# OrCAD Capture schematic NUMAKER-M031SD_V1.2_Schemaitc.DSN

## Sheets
1 Nu-Link2-Me: size A3; title: Nu-Link2-Me; rev: 1.0; company: CMHuang; note: Nu-Link2-Me
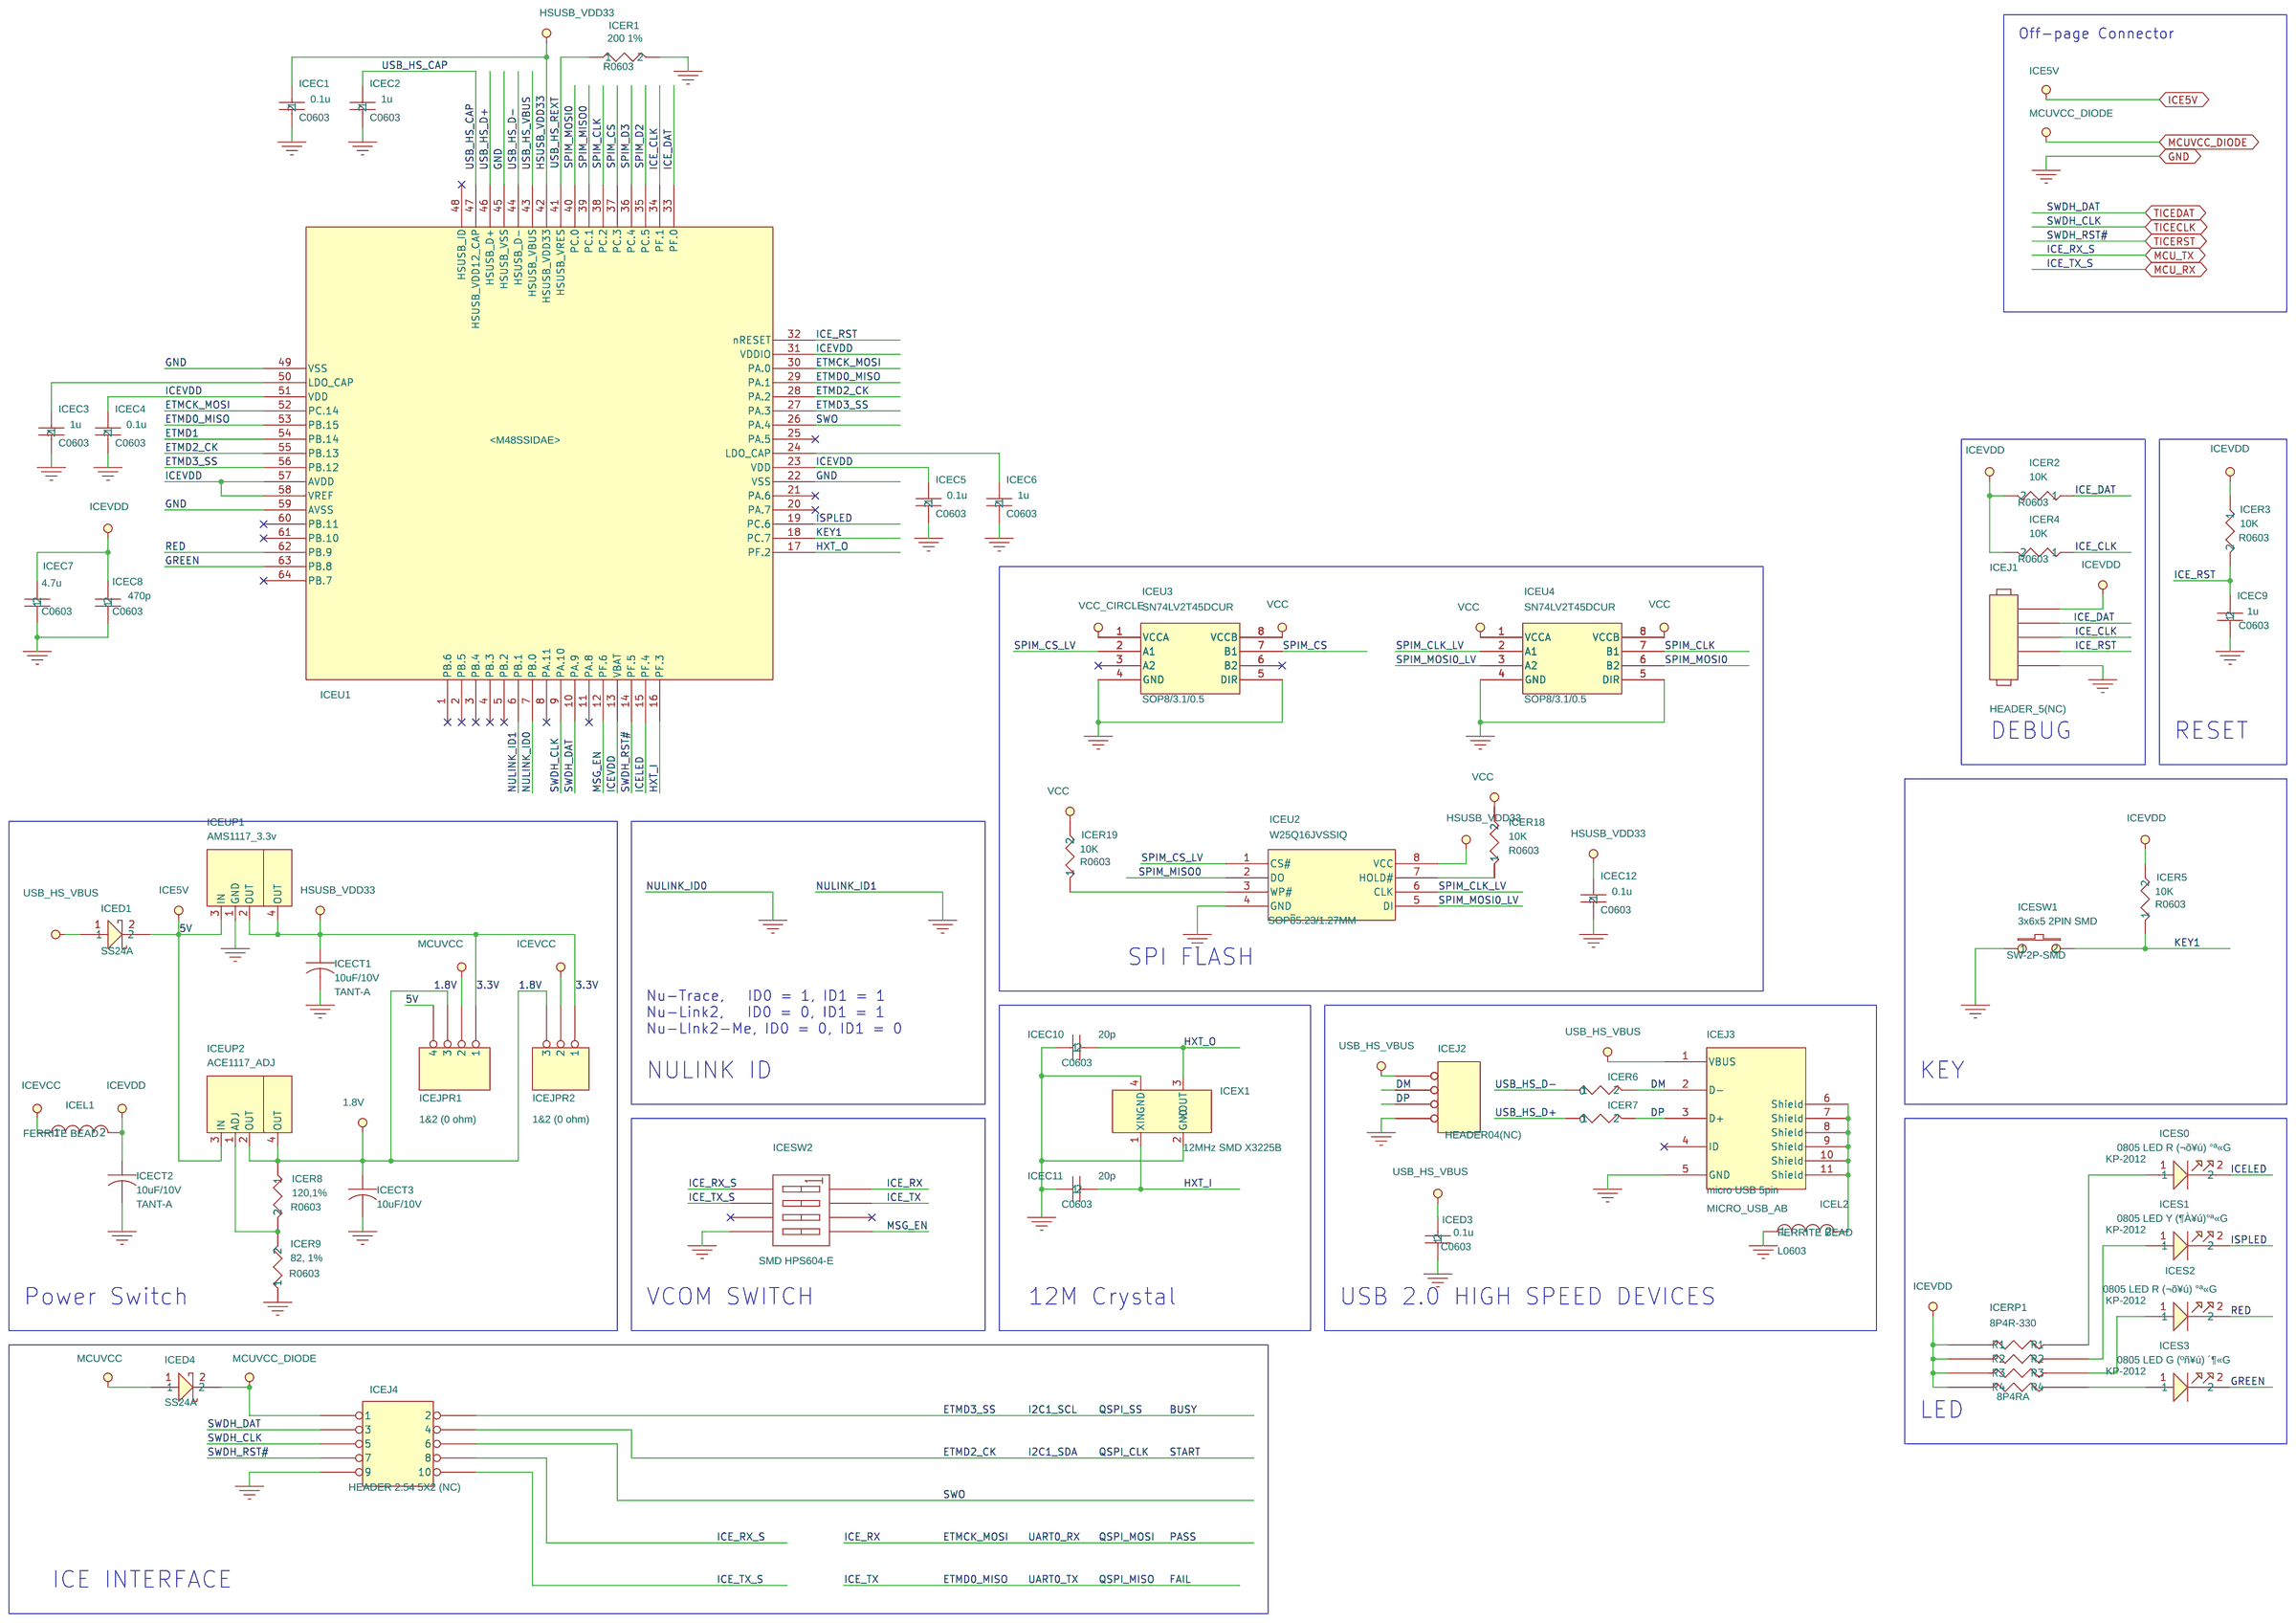
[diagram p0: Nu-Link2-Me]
2 M031SD2AE: size Custom; title: M031SD2AE; rev: v1.2; note: NuMaker-M031SD
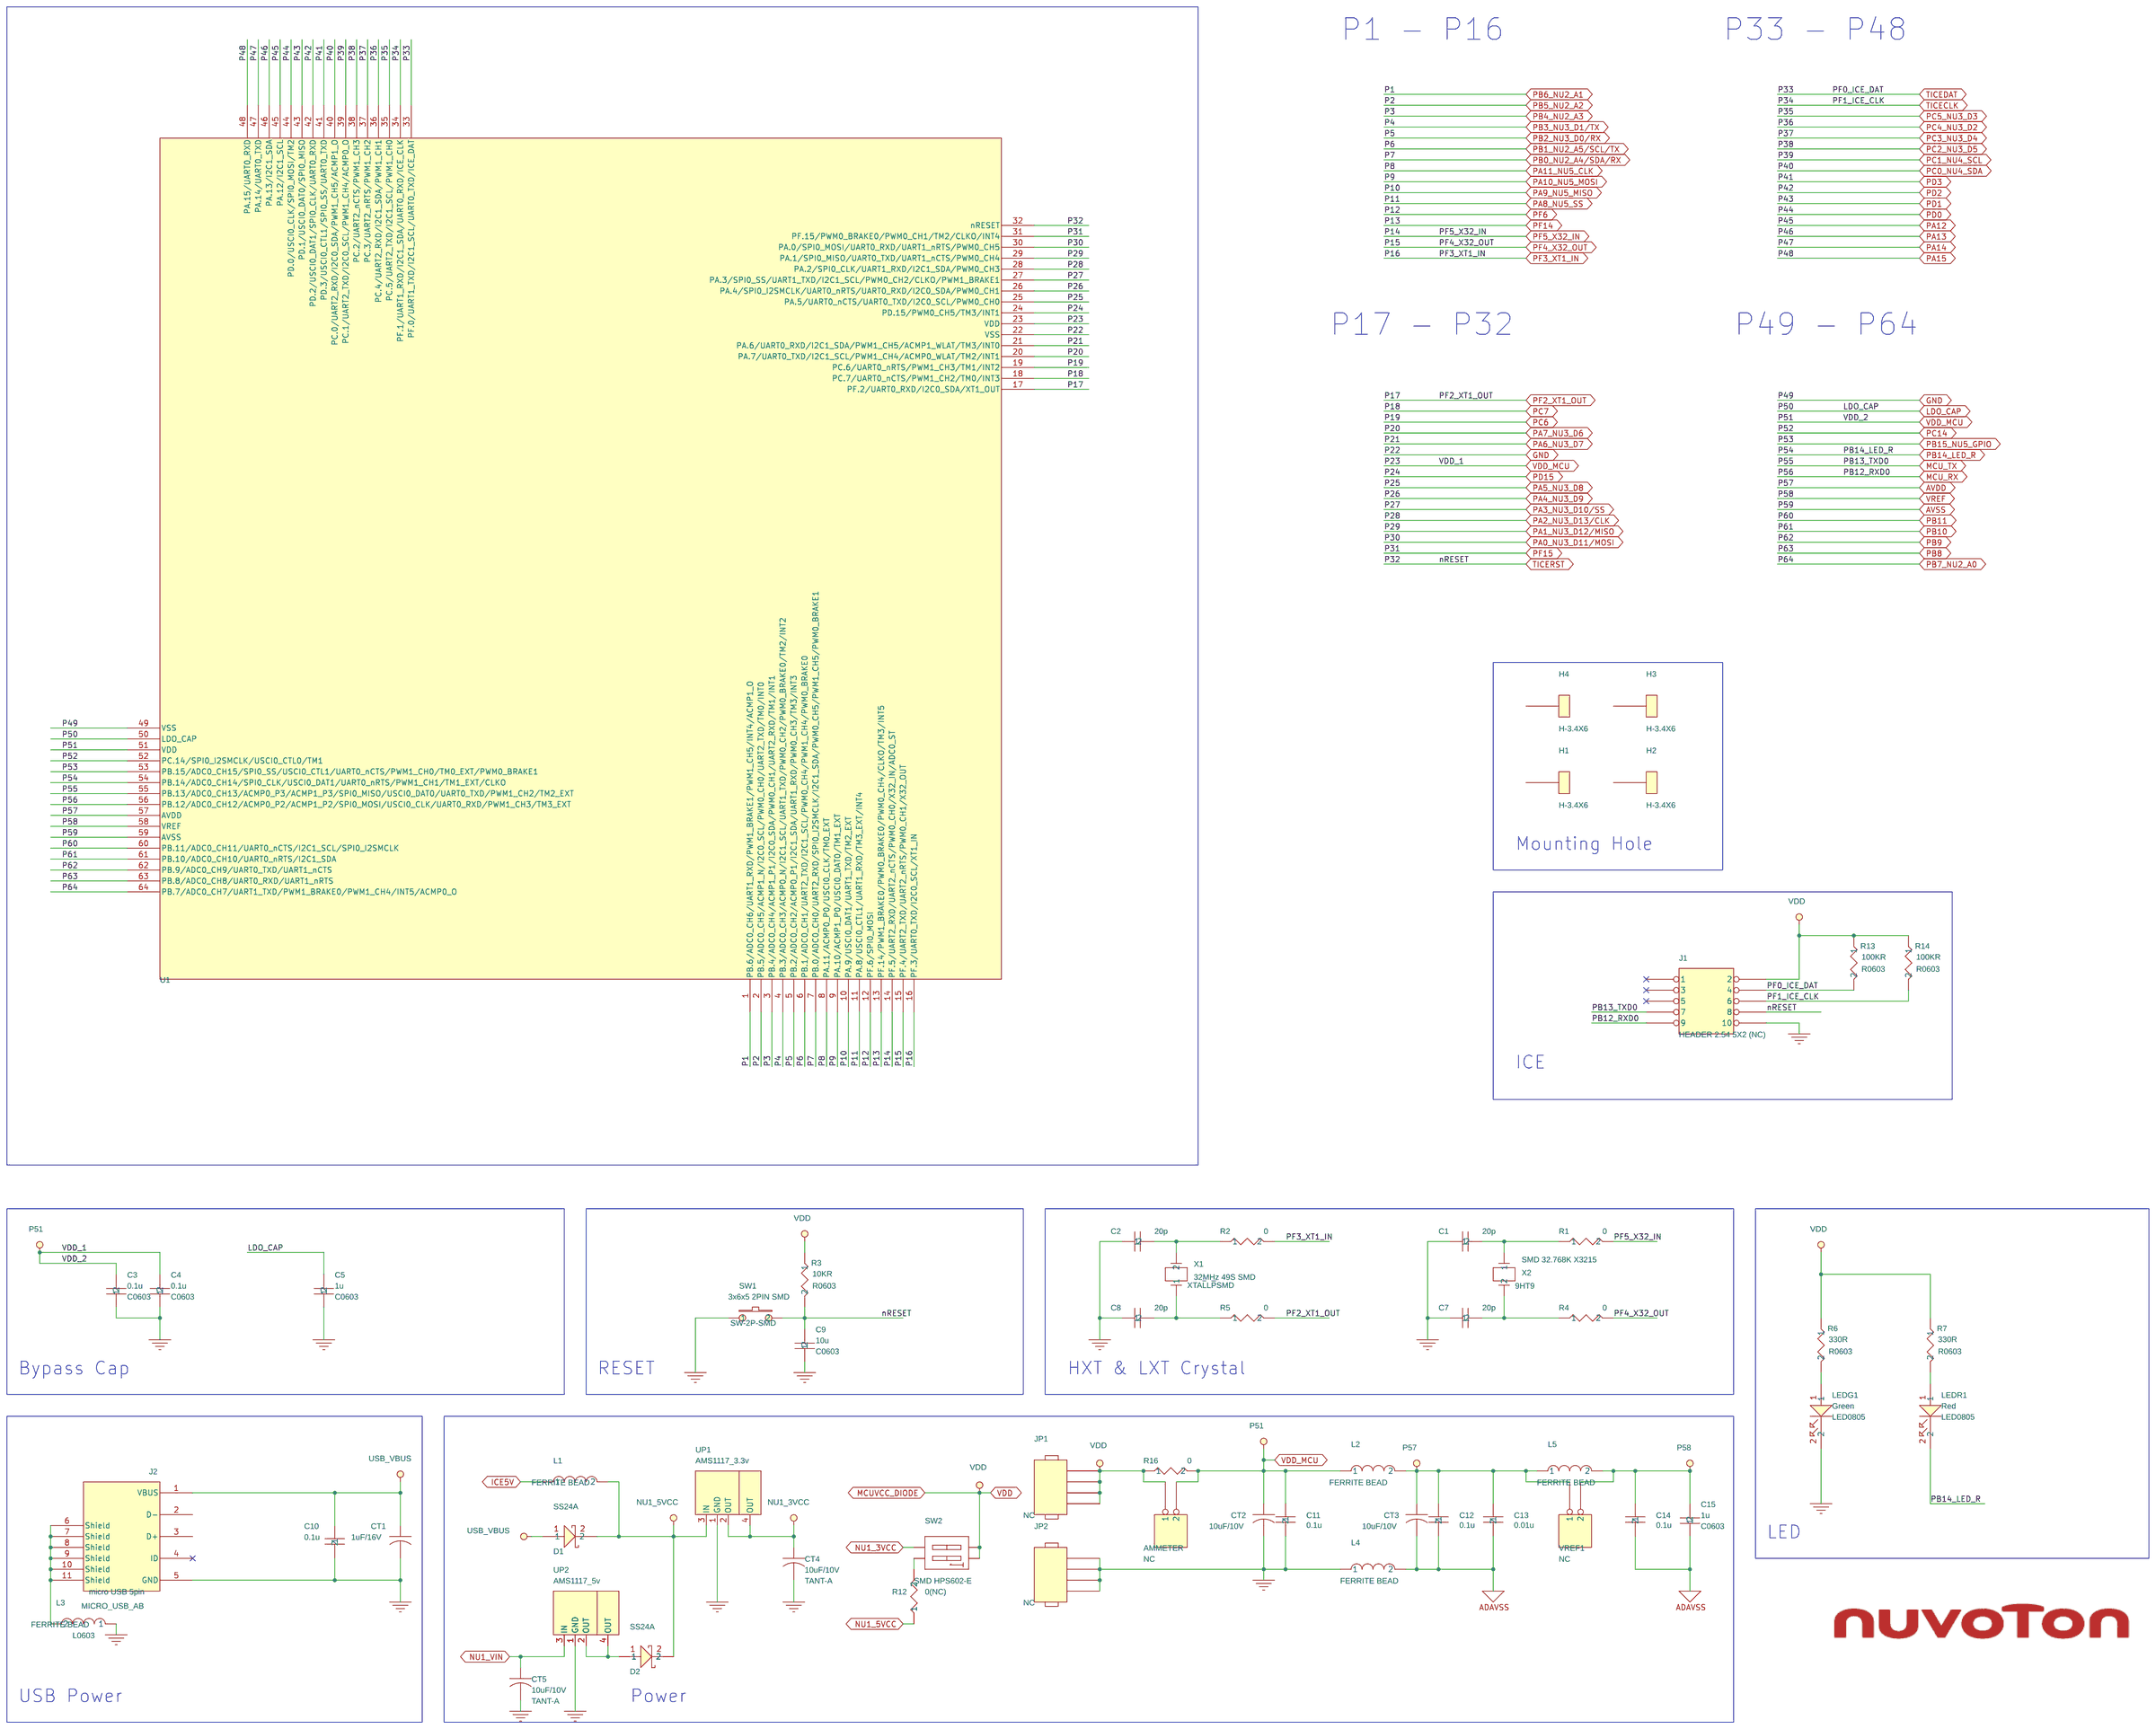
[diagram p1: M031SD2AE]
3 Ext. Connector: size Custom; title: Ext. Connector; rev: v1.2; note: NuMaker-M031SD
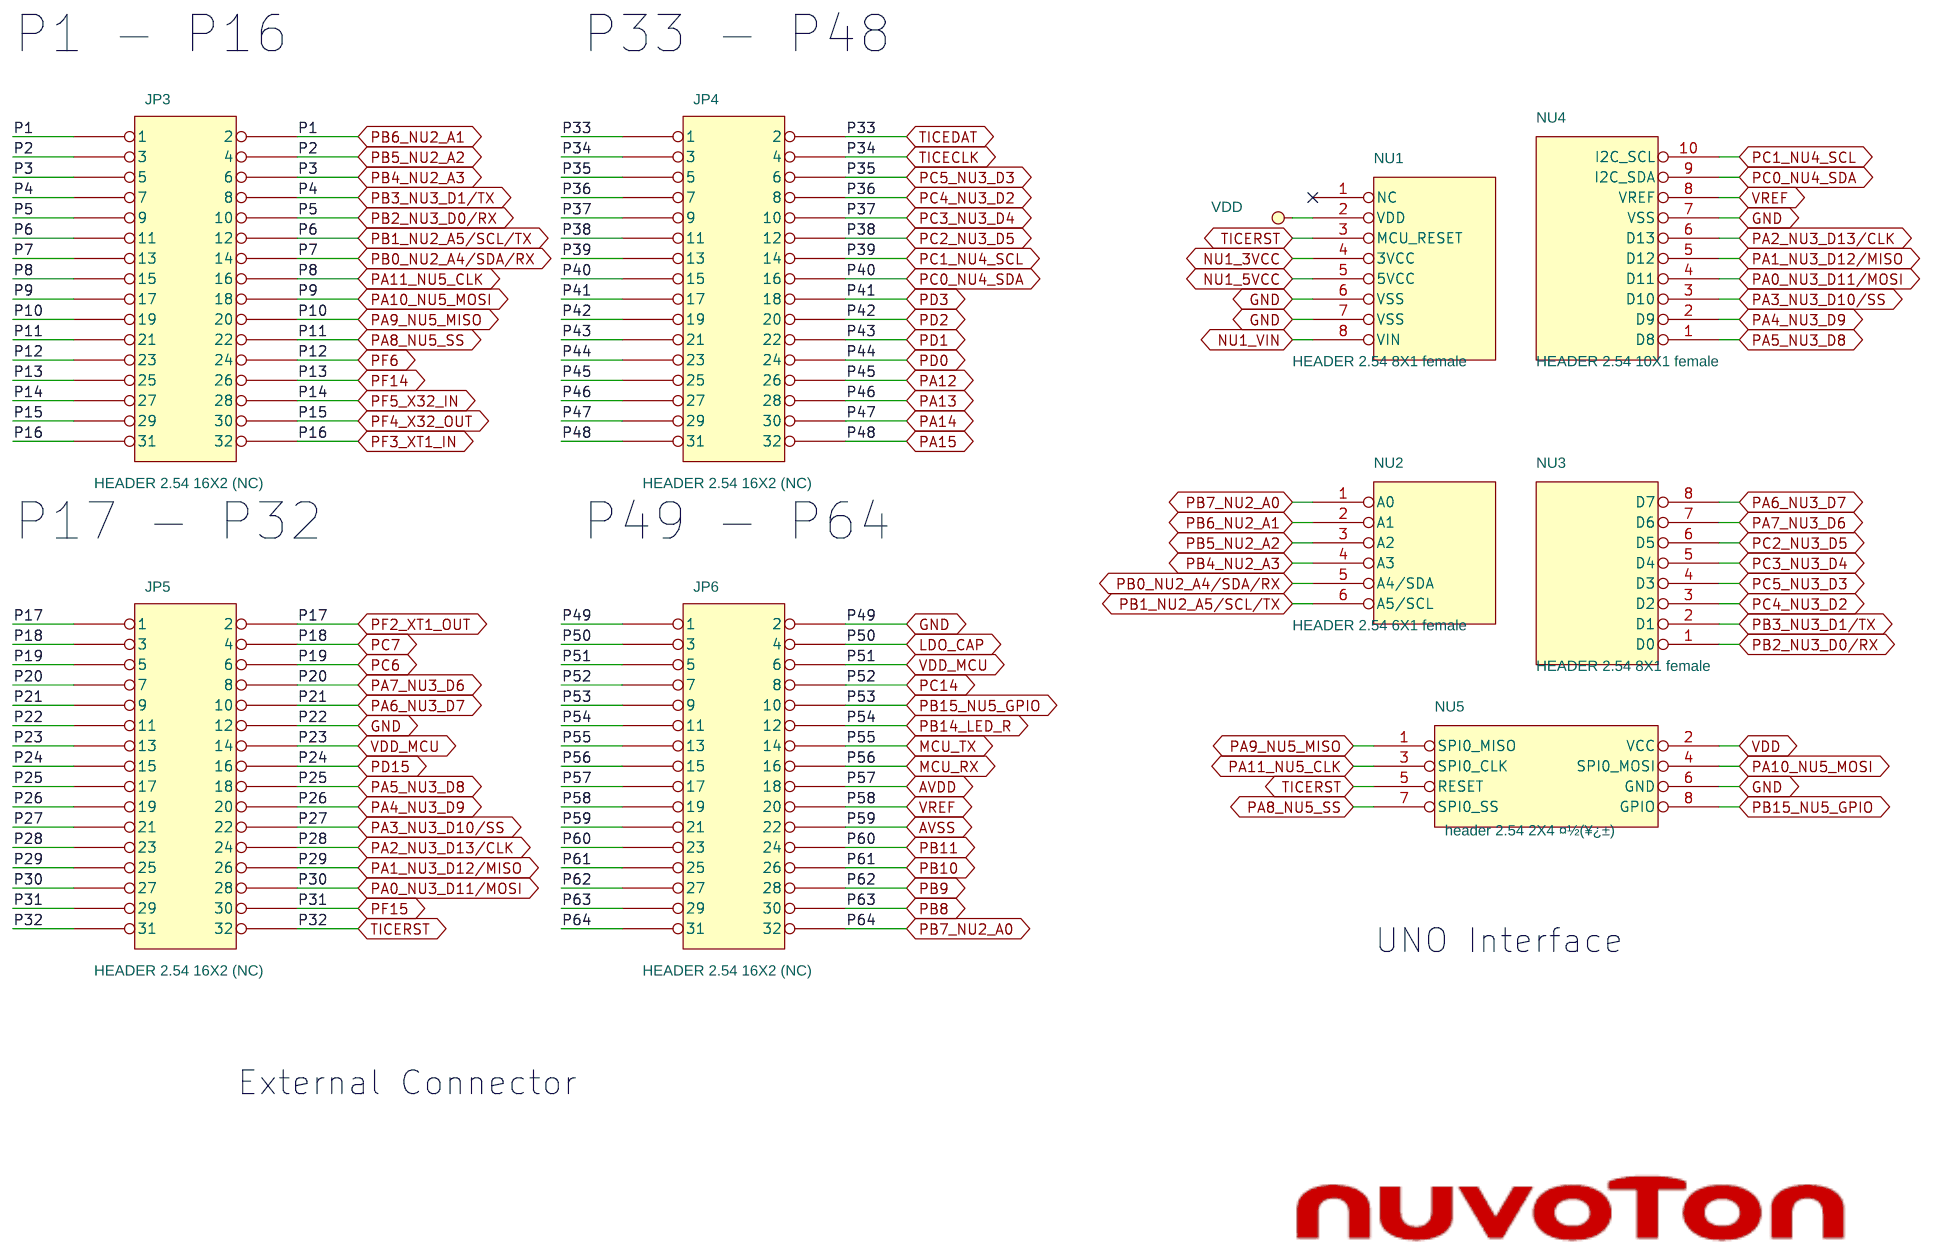
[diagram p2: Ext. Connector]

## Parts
sheet Ext. Connector
JP3  HEADER 2.54 16X2 (NC)  [HEADER16X2]
JP4  HEADER 2.54 16X2 (NC)  [HEADER16X2]
JP5  HEADER 2.54 16X2 (NC)  [HEADER16X2]
JP6  HEADER 2.54 16X2 (NC)  [HEADER16X2]
NU1  HEADER 2.54 8X1 female  [SIP-8P]
NU2  HEADER 2.54 6X1 female  [SIP-6P]
NU3  HEADER 2.54 8X1 female  [SIP-8P]
NU4  HEADER 2.54 10X1 female  [SIP-10P]
NU5  header 2.54 2X4 ¤½(¥¿­±)  [HEADER4X2]
sheet M031SD2AE
AMMETER  NC  [HEADER2X1]
C1  20p  [C0603]
C2  20p  [C0603]
C3  0.1u  [C0603]
C4  0.1u  [C0603]
C5  1u  [C0603]
C7  20p  [C0603]
C8  20p  [C0603]
C9  10u  [C0603]
C10  0.1u  [C0603]
C11  0.1u  [C0603]
C12  0.1u  [C0603]
C13  0.01u  [C0603]
C14  0.1u  [C0603]
C15  1u  [C0603]
CT1  1uF/16V  [TANT-A]
CT2  10uF/10V  [TANT-A]
CT3  10uF/10V  [TANT-A]
CT4  10uF/10V  [TANT-A]
CT5  10uF/10V  [TANT-A]
D1  SS24A  [RB060L]
D2  SS24A  [RB060L]
H1  H-3.4X6  [H-3.4X6]
H2  H-3.4X6  [H-3.4X6]
H3  H-3.4X6  [H-3.4X6]
H4  H-3.4X6  [H-3.4X6]
J1  HEADER 2.54 5X2 (NC)  [HEADER5X2]
J2  micro USB 5pin  [MICRO_USB_AB]
JP1  NC  [header1x4]
JP2  NC  [header1x4]
L1  FERRITE BEAD  [L0603]
L2  FERRITE BEAD  [L0603]
L3  FERRITE BEAD  [L0603]
L4  FERRITE BEAD  [L0603]
L5  FERRITE BEAD  [L0603]
LEDG1  Green  [LED0805]
LEDR1  Red  [LED0805]
R1  0  [R0603]
R2  0  [R0603]
R3  10KR  [R0603]
R4  0  [R0603]
R5  0  [R0603]
R6  330R  [R0603]
R7  330R  [R0603]
R12  0(NC)  [R0603]
R13  100KR  [R0603]
R14  100KR  [R0603]
R16  0  [R0603]
SW1  3x6x5 2PIN SMD  [SW-2P-SMD]
SW2  SMD HPS602-E  [SW1X2]
U1  M031SD2AE  [MCU_LQFP_64_7x7]
UP1  AMS1117_3.3v  [SOT-223-1]
UP2  AMS1117_5v  [SOT-223-1]
VREF1  NC  [HEADER2X1]
X1  32MHz 49S SMD  [XTAL\LP\SMD]
X2  SMD 32.768K X3215  [9HT9]
sheet Nu-Link2-Me
ICEC1  0.1u  [C0603]
ICEC2  1u  [C0603]
ICEC3  1u  [C0603]
ICEC4  0.1u  [C0603]
ICEC5  0.1u  [C0603]
ICEC6  1u  [C0603]
ICEC7  4.7u  [C0603]
ICEC8  470p  [C0603]
ICEC9  1u  [C0603]
ICEC10  20p  [C0603]
ICEC11  20p  [C0603]
ICEC12  0.1u  [C0603]
ICECT1  10uF/10V  [TANT-A]
ICECT2  10uF/10V  [TANT-A]
ICECT3  10uF/10V  [TANT-A]
ICED1  SS24A  [RB060L]
ICED3  0.1u  [C0603]
ICED4  SS24A  [RB060L]
ICEJ1  HEADER_5(NC)  [HEADER5X1]
ICEJ2  HEADER04(NC)  [HEADER04]
ICEJ3  micro USB 5pin  [MICRO_USB_AB]
ICEJ4  HEADER 2.54 5X2 (NC)  [HEADER5X2]
ICEJPR1  1&2 (0 ohm)  [R0603X3]
ICEJPR2  1&2 (0 ohm)  [R0603X2]
ICEL1  FERRITE BEAD  [L0603]
ICEL2  FERRITE BEAD  [L0603]
ICER1  200 1%  [R0603]
ICER2  10K  [R0603]
ICER3  10K  [R0603]
ICER4  10K  [R0603]
ICER5  10K  [R0603]
ICER6  0  [R0603]
ICER7  0  [R0603]
ICER8  120,1%  [R0603]
ICER9  82, 1%  [R0603]
ICER18  10K  [R0603]
ICER19  10K  [R0603]
ICERP1  8P4R-330  [8P4RA]
ICES0  0805 LED R (¬õ¥ú) °ª«G  [KP-2012]
ICES1  0805 LED Y (¶À¥ú)°ª«G  [KP-2012]
ICES2  0805 LED R (¬õ¥ú) °ª«G  [KP-2012]
ICES3  0805 LED G (ºñ¥ú) ´¶«G  [KP-2012]
ICESW1  3x6x5 2PIN SMD  [SW-2P-SMD]
ICESW2  SMD HPS604-E  [SW1X4]
ICEU1  M48SSIDAE  [LQFP64_7x7_M48SSIDAE]
ICEU2  W25Q16JVSSIQ  [SOP8\5.23/1.27MM]
ICEU3  SN74LV2T45DCUR  [SOP8/3.1/0.5]
ICEU4  SN74LV2T45DCUR  [SOP8/3.1/0.5]
ICEUP1  AMS1117_3.3v  [SOT-223-1]
ICEUP2  ACE1117_ADJ  [SOT-223-1]
ICEX1  12MHz SMD X3225B  [CRYSTAL_SMD]

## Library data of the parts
JP3 = HEADER_16X2_2
JP4 = HEADER_16X2
JP5 = HEADER_16X2_3
JP6 = HEADER_16X2_1
NU1 = POWER_CONNECT_0
NU2 = ADC_CONNECT_0
NU3 = PWM0_CONNECT_0
NU4 = PWM1_CONNECT_1
NU5 = NuEdu_NU7
AMMETER = HEADER_2
C1 = C_20p_3
C2 = C_20p
C3 = CAP-C_3: Package: 0603; element_no: C0004
C4 = CAP-C: Package: 0603; element_no: C0004
C5 = CAP-C_1: Package: 0603; element_no: C0006
C7 = C_20p_1
C8 = C_20p_2
C9 = CAP-C_4: Package: 0603; element_no: C0006
C10 = C_0.1u_3: element_no: C0004
C11 = C_0.1u: element_no: C0004
C12 = C_0.1u_2: element_no: C0004
C13 = C_0.1u_4: element_no: C0003
C14 = C_0.1u_1: element_no: C0004
C15 = CAP-C_2: Package: 0603; element_no: C0006
CT1 = C_1uF_16V
CT2-CT5 ICECT1-ICECT3 = C_10uF_10V
D1 ICED1 = D_SS24A
D2 ICED4 = D_SS24A_1
H1-H4 = TEST_POINT
ICEJ4 J1 = HEADER_5X2
ICEJ3 J2 = micro_USB_5pin_0
JP1 JP2 = HEADER_4
L1 = FERRITE_BEAD_4
L2 = FERRITE_BEAD_2
L3 = FERRITE_BEAD_3
ICEL2 L4 = FERRITE_BEAD_1
ICEL1 L5 = FERRITE_BEAD
LEDG1 = LED_0_1: Package: KP-2012; Vendor: Kingbright
LEDR1 = LED_0: Package: KP-2012; Vendor: Kingbright
R1 = R_0_1
R2 = R_0_4
ICER1 R3 = R_0_5: Package: 0603
R4 = R_0_10
R5 = R_0_3
ICER9 R6 = R_0_8: Package: 0603
ICER2 R7 = R_0: Package: 0603
R12 = R_0_7
ICER18 R13 = R_0_6: Package: 0603
R14 = R_0_9: Package: 0603
R16 = R_0_2
ICESW1 SW1 = SW_PUSHBUTTON_0
SW2 = SW_DIP-4_2
U1 = M031SD2AE
ICEUP1 UP1 UP2 = TO-247_Regulator_10
VREF1 = HEADER_2_1
X1 = Xtal_12MHz
X2 = Xtal_32.768K
ICEC1 = CAP-C_9: Package: 0603; element_no: C0004
ICEC2 = CAP-C_10: Package: 0603; element_no: C0006
ICEC3 = CAP-C_11: Package: 0603; element_no: C0006
ICEC4 = CAP-C_2: Package: 0603; element_no: C0004
ICEC5 = CAP-C_4: Package: 0603; element_no: C0004
ICEC6 = CAP-C_5: Package: 0603; element_no: C0006
ICEC7 = CAP-C: Package: 0603
ICEC8 = CAP-C_6: Package: 0603
ICEC9 = CAP-C_7: Package: 0603; element_no: C0006
ICEC10 = CAP-C_3: Package: 0603
ICEC11 = CAP-C_12: Package: 0603
ICEC12 = CAP-C_8: Package: 0603; element_no: C0004
ICED3 = CAP-C_1: Package: 0603; element_no: C0004
ICEJ1 = HEADER_5_v2
ICEJ2 = HEADER_4_v2
ICEJPR1 = HEADER_3_0
ICEJPR2 = HEADER_3
ICER3 = R_0_4: Package: 0603
ICER4 = R_0_7: Package: 0603
ICER5 = R_0_2: Package: 0603
ICER6 = R_33
ICER7 = R_33_1
ICER8 = R_0_3: Package: 0603
ICER19 = R_0_1: Package: 0603
ICERP1 = R-PACK8_0
ICES0 = LED_0_3: Vendor: Kingbright
ICES1 = LED_0_1: Vendor: Kingbright
ICES2 = LED_0: Vendor: Kingbright
ICES3 = LED_0_2: Vendor: Kingbright
ICESW2 = SW_DIP-4_SM
ICEU1 = M487SIDAE_0: M487SIDAE: <M48SSIDAE>
ICEU2 = W25P10_20_40_SOIC_0: Package: SOP8; Vendor: WINBOND
ICEU3 ICEU4 = SN74LV2T45
ICEUP2 = TO-247_Regulator_0
ICEX1 = Crystal_SMD_1

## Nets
1.8V: ICECT3.1 ICEJPR1.3 ICEJPR2.3 ICER8.1 ICEUP2.2(OUT) ICEUP2.4(OUT)
3.3V: ICEC1.1 ICEC12.1 ICECT1.1 ICEJPR1.1 ICEJPR2.1 ICER18.2 ICER19.2 ICEU1.42(HSUSB_VDD33) ICEU2.8(VCC) ICEU3.1(VCCA) ICEU4.1(VCCA) ICEUP1.2(OUT) ICEUP1.4(OUT)
AVDD: C12.1 C13.1 CT3.1 JP6.17 JP6.18 L2.2 L5.1 U1.57(AVDD) VREF1.1
AVSS: C12.2 C13.2 C14.2 C15.1 CT3.2 JP6.21 JP6.22 L4.2 U1.59(AVSS)
GND: C1.1 C2.1 C3.1 C4.1 C5.1 C7.1 C8.1 C9.1 C10.2 C11.2 CT1.2 CT2.2 CT4.2 CT5.2 ICEC1.2 ICEC2.2 ICEC3.2 ICEC4.2 ICEC5.2 ICEC6.2 ICEC7.1 ICEC8.1 ICEC9.1 ICEC10.1 ICEC11.1 ICEC12.2 ICECT1.2 ICECT2.2 ICECT3.2 ICED3.1 ICEJ1.5 ICEJ2.4 ICEJ3.5(GND) ICEJ4.9 ICEL2.1 ICER1.2 ICER9.1 ICESW1.1 ICESW2.4(A4) ICEU1.6(PB.1) ICEU1.7(PB.0) ICEU1.22(VSS) ICEU1.45(HSUSB_VSS) ICEU1.49(VSS) ICEU1.59(AVSS) ICEU2.4(GND) ICEU3.4(GND) ICEU3.5(DIR) ICEU4.4(GND) ICEU4.5(DIR) ICEUP1.1(GND) ICEX1.2(GND) ICEX1.4(GND) J1.10 J2.5(GND) JP2.1 JP2.2 JP2.3 JP2.4 JP5.11 JP5.12 JP6.1 JP6.2 L3.1 L4.1 LEDG1.2 NU1.6(VSS) NU1.7(VSS) NU4.7(VSS) NU5.6(GND) SW1.1 U1.22(VSS) U1.49(VSS) UP1.1(GND) UP2.1(GND)
VDD: AMMETER.1 ICED4.2 ICEJ4.1 J1.2 JP1.1 JP1.2 JP1.3 JP1.4 NU1.2(VDD) NU5.2(VCC) R3.1 R6.1 R7.1 R13.1 R14.1 R16.1 SW2.3(B1) SW2.4(B2)
VDD_MCU: AMMETER.2 C3.2 C4.2 C11.1 CT2.1 JP5.13 JP5.14 JP6.5 JP6.6 L2.1 R16.2 U1.23(VDD) U1.51(VDD)
BUSY: ICEJ4.2 ICEU1.27(PA.3) ICEU1.56(PB.12)
DM: ICEJ2.2 ICEJ3.2(D-) ICER6.2
DP: ICEJ2.3 ICEJ3.3(D+) ICER7.2
ETMD1: ICEU1.54(PB.14)
ETMD2_CK: ICEJ4.4 ICEU1.28(PA.2) ICEU1.55(PB.13)
GREEN: ICES3.2 ICEU1.63(PB.8)
HXT_I: ICEC11.2 ICEU1.16(PF.3) ICEX1.1(XIN)
HXT_O: ICEC10.2 ICEU1.17(PF.2) ICEX1.3(XOUT)
ICE5V: ICED1.2 ICEJPR1.4 ICEUP1.3(IN) ICEUP2.3(IN) L1.1
ICE_CLK: ICEJ1.3 ICER4.1 ICEU1.34(PF.1)
ICE_DAT: ICEJ1.2 ICER2.1 ICEU1.33(PF.0)
ICE_RST: ICEC9.2 ICEJ1.4 ICER3.2 ICEU1.32(nRESET)
ICE_RX: ICESW2.8(B1) ICEU1.30(PA.0) ICEU1.52(PC.14)
ICE_TX: ICESW2.7(B2) ICEU1.29(PA.1) ICEU1.53(PB.15)
ICELED: ICES0.2 ICEU1.15(PF.4)
ICEVCC: ICEJPR2.2 ICEL1.1
ICEVDD: ICEC4.1 ICEC5.1 ICEC7.2 ICEC8.2 ICECT2.1 ICEJ1.1 ICEL1.2 ICER2.2 ICER3.1 ICER4.2 ICER5.2 ICERP1.1(R1) ICERP1.3(R2) ICERP1.5(R3) ICERP1.7(R4) ICEU1.13(VBAT) ICEU1.23(VDD) ICEU1.31(VDDIO) ICEU1.51(VDD) ICEU1.57(AVDD) ICEU1.58(VREF) ICEU3.8(VCCB) ICEU4.8(VCCB)
ISPLED: ICES1.2 ICEU1.19(PC.6)
KEY1: ICER5.1 ICESW1.2 ICEU1.18(PC.7)
LDO_CAP: C5.2 JP6.3 JP6.4 U1.50(LDO_CAP)
MCU_RX: ICEJ4.10 ICESW2.2(A2) J1.9 JP6.15 JP6.16 U1.56(PB.12/ADC0_CH12/ACMP0_P2/ACMP1_P2/SPI0_MOSI/USCI0_CLK/UART0_RXD/PWM1_CH3/TM3_EXT)
MCU_TX: ICEJ4.8 ICESW2.1(A1) J1.7 JP6.13 JP6.14 U1.55(PB.13/ADC0_CH13/ACMP0_P3/ACMP1_P3/SPI0_MISO/USCI0_DAT0/UART0_TXD/PWM1_CH2/TM2_EXT)
MCUVCC: ICED4.1 ICEJPR1.2
MSG_EN: ICESW2.5(B4) ICEU1.12(PF.6)
NU1_3VCC: CT4.1 NU1.4(3VCC) SW2.2(A2) UP1.2(OUT) UP1.4(OUT)
NU1_5VCC: D1.2 D2.2 L1.2 NU1.5(5VCC) R12.1 UP1.3(IN)
NU1_VIN: CT5.1 NU1.8(VIN) UP2.3(IN)
PA0_NU3_D11/MOSI: JP5.27 JP5.28 NU4.4(D11) U1.30(PA.0/SPI0_MOSI/UART0_RXD/UART1_nRTS/PWM0_CH5)
PA1_NU3_D12/MISO: JP5.25 JP5.26 NU4.5(D12) U1.29(PA.1/SPI0_MISO/UART0_TXD/UART1_nCTS/PWM0_CH4)
PA2_NU3_D13/CLK: JP5.23 JP5.24 NU4.6(D13) U1.28(PA.2/SPI0_CLK/UART1_RXD/I2C1_SDA/PWM0_CH3)
PA3_NU3_D10/SS: JP5.21 JP5.22 NU4.3(D10) U1.27(PA.3/SPI0_SS/UART1_TXD/I2C1_SCL/PWM0_CH2/CLKO/PWM1_BRAKE1)
PA4_NU3_D9: JP5.19 JP5.20 NU4.2(D9) U1.26(PA.4/SPI0_I2SMCLK/UART0_nRTS/UART0_RXD/I2C0_SDA/PWM0_CH1)
PA5_NU3_D8: JP5.17 JP5.18 NU4.1(D8) U1.25(PA.5/UART0_nCTS/UART0_TXD/I2C0_SCL/PWM0_CH0)
PA6_NU3_D7: JP5.9 JP5.10 NU3.8(D7) U1.21(PA.6/UART0_RXD/I2C1_SDA/PWM1_CH5/ACMP1_WLAT/TM3/INT0)
PA7_NU3_D6: JP5.7 JP5.8 NU3.7(D6) U1.20(PA.7/UART0_TXD/I2C1_SCL/PWM1_CH4/ACMP0_WLAT/TM2/INT1)
PA8_NU5_SS: JP3.21 JP3.22 NU5.7(SPI0_SS) U1.11(PA.8/USCI0_CTL1/UART1_RXD/TM3_EXT/INT4)
PA9_NU5_MISO: JP3.19 JP3.20 NU5.1(SPI0_MISO) U1.10(PA.9/USCI0_DAT1/UART1_TXD/TM2_EXT)
PA10_NU5_MOSI: JP3.17 JP3.18 NU5.4(SPI0_MOSI) U1.9(PA.10/ACMP1_P0/USCI0_DAT0/TM1_EXT)
PA11_NU5_CLK: JP3.15 JP3.16 NU5.3(SPI0_CLK) U1.8(PA.11/ACMP0_P0/USCI0_CLK/TM0_EXT)
PA12: JP4.25 JP4.26 U1.45(PA.12/I2C1_SCL)
PA13: JP4.27 JP4.28 U1.46(PA.13/I2C1_SDA)
PA14: JP4.29 JP4.30 U1.47(PA.14/UART0_TXD)
PA15: JP4.31 JP4.32 U1.48(PA.15/UART0_RXD)
PB0_NU2_A4/SDA/RX: JP3.13 JP3.14 NU2.5(A4/SDA) U1.7(PB.0/ADC0_CH0/UART2_RXD/SPI0_I2SMCLK/I2C1_SDA/PWM0_CH5/PWM1_CH5/PWM0_BRAKE1)
PB1_NU2_A5/SCL/TX: JP3.11 JP3.12 NU2.6(A5/SCL) U1.6(PB.1/ADC0_CH1/UART2_TXD/I2C1_SCL/PWM0_CH4/PWM1_CH4/PWM0_BRAKE0)
PB2_NU3_D0/RX: JP3.9 JP3.10 NU3.1(D0) U1.5(PB.2/ADC0_CH2/ACMP0_P1/I2C1_SDA/UART1_RXD/PWM0_CH3/TM3/INT3)
PB3_NU3_D1/TX: JP3.7 JP3.8 NU3.2(D1) U1.4(PB.3/ADC0_CH3/ACMP0_N/I2C1_SCL/UART1_TXD/PWM0_CH2/PWM0_BRAKE0/TM2/INT2)
PB4_NU2_A3: JP3.5 JP3.6 NU2.4(A3) U1.3(PB.4/ADC0_CH4/ACMP1_P1/I2C0_SDA/PWM0_CH1/UART2_RXD/TM1/INT1)
PB5_NU2_A2: JP3.3 JP3.4 NU2.3(A2) U1.2(PB.5/ADC0_CH5/ACMP1_N/I2C0_SCL/PWM0_CH0/UART2_TXD/TM0/INT0)
PB6_NU2_A1: JP3.1 JP3.2 NU2.2(A1) U1.1(PB.6/ADC0_CH6/UART1_RXD/PWM1_BRAKE1/PWM1_CH5/INT4/ACMP1_O)
PB7_NU2_A0: JP6.31 JP6.32 NU2.1(A0) U1.64(PB.7/ADC0_CH7/UART1_TXD/PWM1_BRAKE0/PWM1_CH4/INT5/ACMP0_O)
PB8: JP6.29 JP6.30 U1.63(PB.8/ADC0_CH8/UART0_RXD/UART1_nRTS)
PB9: JP6.27 JP6.28 U1.62(PB.9/ADC0_CH9/UART0_TXD/UART1_nCTS)
PB10: JP6.25 JP6.26 U1.61(PB.10/ADC0_CH10/UART0_nRTS/I2C1_SDA)
PB11: JP6.23 JP6.24 U1.60(PB.11/ADC0_CH11/UART0_nCTS/I2C1_SCL/SPI0_I2SMCLK)
PB14_LED_R: JP6.11 JP6.12 LEDR1.2 U1.54(PB.14/ADC0_CH14/SPI0_CLK/USCI0_DAT1/UART0_nRTS/PWM1_CH1/TM1_EXT/CLKO)
PB15_NU5_GPIO: JP6.9 JP6.10 NU5.8(GPIO) U1.53(PB.15/ADC0_CH15/SPI0_SS/USCI0_CTL1/UART0_nCTS/PWM1_CH0/TM0_EXT/PWM0_BRAKE1)
PC0_NU4_SDA: JP4.15 JP4.16 NU4.9(I2C_SDA) U1.40(PC.0/UART2_RXD/I2C0_SDA/PWM1_CH5/ACMP1_O)
PC1_NU4_SCL: JP4.13 JP4.14 NU4.10(I2C_SCL) U1.39(PC.1/UART2_TXD/I2C0_SCL/PWM1_CH4/ACMP0_O)
PC2_NU3_D5: JP4.11 JP4.12 NU3.6(D5) U1.38(PC.2/UART2_nCTS/PWM1_CH3)
PC3_NU3_D4: JP4.9 JP4.10 NU3.5(D4) U1.37(PC.3/UART2_nRTS/PWM1_CH2)
PC4_NU3_D2: JP4.7 JP4.8 NU3.3(D2) U1.36(PC.4/UART2_RXD/I2C1_SDA/PWM1_CH1)
PC5_NU3_D3: JP4.5 JP4.6 NU3.4(D3) U1.35(PC.5/UART2_TXD/I2C1_SCL/PWM1_CH0)
PC6: JP5.5 JP5.6 U1.19(PC.6/UART0_nRTS/PWM1_CH3/TM1/INT2)
PC7: JP5.3 JP5.4 U1.18(PC.7/UART0_nCTS/PWM1_CH2/TM0/INT3)
PC14: JP6.7 JP6.8 U1.52(PC.14/SPI0_I2SMCLK/USCI0_CTL0/TM1)
PD0: JP4.23 JP4.24 U1.44(PD.0/USCI0_CLK/SPI0_MOSI/TM2)
PD1: JP4.21 JP4.22 U1.43(PD.1/USCI0_DAT0/SPI0_MISO)
PD2: JP4.19 JP4.20 U1.42(PD.2/USCI0_DAT1/SPI0_CLK/UART0_RXD)
PD3: JP4.17 JP4.18 U1.41(PD.3/USCI0_CTL1/SPI0_SS/UART0_TXD)
PD15: JP5.15 JP5.16 U1.24(PD.15/PWM0_CH5/TM3/INT1)
PF2_XT1_OUT: JP5.1 JP5.2 R5.2 U1.17(PF.2/UART0_RXD/I2C0_SDA/XT1_OUT)
PF3_XT1_IN: JP3.31 JP3.32 R2.2 U1.16(PF.3/UART0_TXD/I2C0_SCL/XT1_IN)
PF4_X32_OUT: JP3.29 JP3.30 R4.2 U1.15(PF.4/UART2_TXD/UART2_nRTS/PWM0_CH1/X32_OUT)
PF5_X32_IN: JP3.27 JP3.28 R1.2 U1.14(PF.5/UART2_RXD/UART2_nCTS/PWM0_CH0/X32_IN/ADC0_ST)
PF6: JP3.23 JP3.24 U1.12(PF.6/SPI0_MOSI)
PF14: JP3.25 JP3.26 U1.13(PF.14/PWM1_BRAKE0/PWM0_BRAKE0/PWM0_CH4/CLKO/TM3/INT5)
PF15: JP5.29 JP5.30 U1.31(PF.15/PWM0_BRAKE0/PWM0_CH1/TM2/CLKO/INT4)
RED: ICES2.2 ICEU1.62(PB.9)
SPIM_CLK: ICEU1.38(PC.2) ICEU4.7(B1)
SPIM_CLK_LV: ICEU2.6(CLK) ICEU4.2(A1)
SPIM_CS: ICEU1.37(PC.3) ICEU3.7(B1)
SPIM_CS_LV: ICEU2.1(CS#) ICEU3.2(A1)
SPIM_D2: ICEU1.35(PC.5)
SPIM_D3: ICEU1.36(PC.4)
SPIM_MISO0: ICEU1.39(PC.1) ICEU2.2(DO)
SPIM_MOSI0: ICEU1.40(PC.0) ICEU4.6(B2)
SPIM_MOSI0_LV: ICEU2.5(DI) ICEU4.3(A2)
SWO: ICEJ4.6 ICEU1.26(PA.4)
TICECLK: ICEJ4.5 ICEU1.9(PA.10) J1.6 JP4.3 JP4.4 R14.2 U1.34(PF.1/UART1_RXD/I2C1_SDA/UART0_RXD/ICE_CLK)
TICEDAT: ICEJ4.3 ICEU1.10(PA.9) J1.4 JP4.1 JP4.2 R13.2 U1.33(PF.0/UART1_TXD/I2C1_SCL/UART0_TXD/ICE_DAT)
TICERST: C9.2 ICEJ4.7 ICEU1.14(PF.5) J1.8 JP5.31 JP5.32 NU1.3(MCU_RESET) NU5.5(RESET) R3.2 SW1.2 U1.32(nRESET)
USB_HS_CAP: ICEC2.1 ICEU1.47(HSUSB_VDD12_CAP)
USB_HS_D+: ICER7.1 ICEU1.46(HSUSB_D+)
USB_HS_D-: ICER6.1 ICEU1.44(HSUSB_D-)
USB_HS_REXT: ICER1.1 ICEU1.41(HSUSB_VRES)
USB_HS_VBUS: ICED1.1 ICED3.2 ICEJ2.1 ICEJ3.1(VBUS) ICEU1.43(HSUSB_VBUS)
USB_VBUS: C10.1 CT1.1 D1.1 J2.1(VBUS)
VREF: C14.1 C15.2 JP6.19 JP6.20 L5.2 NU4.8(VREF) U1.58(VREF) VREF1.2
N16825237: LEDG1.1 R6.2
N16825240: LEDR1.1 R7.2
N16840819: ICEC6.1 ICEU1.24(LDO_CAP)
N16840960: ICEC3.1 ICEU1.50(LDO_CAP)
N17019924: ICER8.2 ICER9.2 ICEUP2.1(ADJ)
N17029977: ICERP1.8(R4) ICES3.1
N17029979: ICERP1.6(R3) ICES2.1
N17030004: ICERP1.4(R2) ICES1.1
N17030010: ICERP1.2(R1) ICES0.1
N17042369: ICEJ3.6(Shield) ICEJ3.7(Shield) ICEJ3.8(Shield) ICEJ3.9(Shield) ICEJ3.10(Shield) ICEJ3.11(Shield) ICEL2.2
N17110356: J2.6(Shield) J2.7(Shield) J2.8(Shield) J2.9(Shield) J2.10(Shield) J2.11(Shield) L3.2
N17155328: ICER18.1 ICEU2.7(HOLD#)
N17155343: ICER19.1 ICEU2.3(WP#)
N17159369: C8.2 R5.1 X1.1
N17159371: C2.2 R2.1 X1.2
N17159463: C1.2 R1.1 X2.1
N17159465: C7.2 R4.1 X2.2
N17195024: R12.2 SW2.1(A1)
N17195076: D2.1 UP2.2(OUT) UP2.4(OUT)

Not connected (* = marked no-connect by the designer): H1 1; H2 1; H3 1; H4 1; ICEJ3 4(ID)*; ICESW2 3(A3)* 6(B3)*; ICEU1 1(PB.6)* 2(PB.5)* 3(PB.4)* 4(PB.3)* 5(PB.2)* 8(PA.11)* 11(PA.8)* 20(PA.7)* 21(PA.6)* 25(PA.5)* 48(HSUSB_ID)* 60(PB.11)* 61(PB.10)* 64(PB.7)*; ICEU3 3(A2)* 6(B2)*; J1 1* 3* 5*; J2 2(D-) 3(D+) 4(ID)*; NU1 1(NC)*

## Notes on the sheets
sheet 1
- Off-page Connector
- DEBUG
- RESET
- SPI FLASH
- Nu-Trace,   ID0 = 1, ID1 = 1
  Nu-Link2,   ID0 = 0, ID1 = 1
  Nu-LInk2-Me, ID0 = 0, ID1 = 0
- NULINK ID
- KEY
- Power Switch
- VCOM SWITCH
- 12M Crystal
- USB 2.0 HIGH SPEED DEVICES
- LED
- ICE INTERFACE
sheet 2
- P1 - P16
- P33 - P48
- P17 - P32
- P49 - P64
- Mounting Hole
- ICE
- Bypass Cap
- RESET
- HXT & LXT Crystal
- LED
- USB Power
- Power
sheet 3
- P1 - P16
- P33 - P48
- P17 - P32
- P49 - P64
- UNO Interface
- External Connector
